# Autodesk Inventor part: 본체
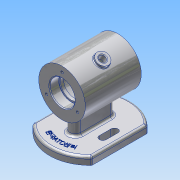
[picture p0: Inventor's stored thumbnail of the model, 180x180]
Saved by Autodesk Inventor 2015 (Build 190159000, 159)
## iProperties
Created: 2022-02
Part Number: 본체
Material: 알루미늄 6061
Document SubType Name: Modeling
Designer: 학생용
Density: 2.7 g/cm^3
Appearance: 알루미늄 - 평지
Mass: 495.267 g
Surface Area: 489.781 cm^2
Volume: 183.432 cm^3
Author: 학생용
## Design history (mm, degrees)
sketch "스케치1"
  geometry: L1 (0, 0)-(72, 0); L2 (72, 0)-(72, 30); L3 (72, 30)-(0, 30); L4 (0, 30)-(0, 0); L5 (0, 16)-(12, 16); L6 (12, 16)-(12, 14); L7 (12, 14)-(16, 14); L8 (16, 14)-(16, 25); L9 (16, 25)-(56, 25); L10 (56, 25)-(56, 14); L11 (56, 14)-(60, 14); L12 (60, 14)-(60, 16); L13 (60, 16)-(72, 16)
  constraints: 26 end point, 9 perpendicular, 6 point on line, 2 collinear, 2 horizontal
  dimensions: "d0" = 72 distance of L2.end L3.end; "d1" = 60 diameter of L3 L1; "d2" = 50 diameter of L9 L1; "d3" = 32 diameter of L13 L1; "d4" = 28 diameter of L11 L1; "d5" = 40 distance of L8.end L9.end; "d6" = 12 distance of L5.start L5.end
revolve "회전1" sketch "스케치1" stored, may be unused: angle "d7" = 90 deg
node "작업 평면2"
  node "작업 평면1"
sketch "스케치2"
  geometry: L1 (-0.504, -38)-(-71.496, -38); L2 (-0.504, 38)-(-71.496, 38); L3 (0, 30)-(0, -30) reference; L4 (-72, 30)-(-72, -30) reference; L5 (0, -30)-(-72, -30) reference; A1 r 52 centre (-36, 0) between (-0.504, -38) and (-0.504, 38); A2 r 52 centre (-36, 0) between (-71.496, 38) and (-71.496, -38); 4 further points
  constraints: 4 end point, 4 point on circle, 3 midpoint, 3 vertical alignment, 2 centre point, 2 horizontal, 1 coincident, 1 concentric, 1 horizontal alignment, 1 parallel
  dimensions: "d9" = 76 distance between parallel lines of L2 L1; "d10" = 52 radius of A1
extrude "돌출1" join sketch "스케치2" distance "d11" = 10; taper "d12" = 0 deg
sketch "스케치3"
  geometry: L1 (28.5, 28.5)-(43.5, 28.5); L2 (28.5, 19.5)-(43.5, 19.5); L3 (0.504, 38)-(71.496, 38) reference; A1 r 4.5 centre (28.5, 24) between (28.5, 28.5) and (28.5, 19.5); A2 r 4.5 centre (43.5, 24) between (43.5, 19.5) and (43.5, 28.5); 3 further points
  constraints: 4 end point, 4 point on circle, 3 vertical alignment, 2 centre point, 2 horizontal, 2 midpoint, 1 equal radius, 1 parallel, 1 tangent
  dimensions: "d13" = 15 distance of A2.centre A1.centre; "d14" = 9 distance between parallel lines of L2 L1; "d15" = 24 vertical distance of A1.centre point (0, 0)
extrude "돌출2" cut sketch "스케치3" distance "d16" = 10; taper "d17" = 0 deg
node "작업 평면3"
node "작업 평면4"
sketch "스케치4"
  geometry: L1 (28.5, 28.5)-(43.5, 28.5) reference; C1 r 42.5 at (36, 0); 2 further points
  constraints: 1 centre point, 1 horizontal alignment, 1 midpoint, 1 vertical alignment, 1 other
  dimensions: "d19" = 85 diameter of C1
feature "엠보싱1" sketch "스케치4" dims "d9" = 76, "d10" = 52, "d20" = 0.5, "d21" = 0
sketch "스케치5"
  geometry: L1 (17, 7)-(55, 7); L2 (17, -7)-(55, -7); L3 (0.504, 38)-(71.496, 38) reference; A1 r 7 centre (17, 0) between (17, 7) and (17, -7); A2 r 7 centre (55, 0) between (55, -7) and (55, 7); 3 further points
  constraints: 4 end point, 4 point on circle, 4 tangent, 2 centre point, 2 horizontal, 2 midpoint, 1 horizontal alignment, 1 vertical alignment
  dimensions: "d22" = 14 distance between parallel lines of L2 L1; "d23" = 38 distance of L2.start L2.end
extrude "돌출3" join sketch "스케치5" stored distance "d24" = 10; taper "d25" = 0 deg
node "작업 평면5"
sketch "스케치6"
  geometry: L1 (0, 0)-(0, 30); L2 (0, 0)-(16.5, 28.579); 1 further point
  constraints: 4 end point, 1 vertical, 1 vertical alignment, 1 other
  dimensions: "d26" = 30 deg angle of L2 L1; "d27" = 33 distance of L1.start L2.end
node "작업 평면6"
sketch "스케치7"
  geometry: C1 r 8 at (0, 0); C2 r 4 at (0, 0); 2 further points
  constraints: 2 centre point, 2 coincident
  dimensions: "d28" = 16 diameter of C1; "d29" = 8 diameter of C2
extrude "돌출4" join sketch "스케치7" stored distance "d30" = 10; taper "d31" = 0 deg
extrude "돌출5" cut sketch "스케치7" stored distance "d32" = 8; taper "d33" = 0 deg
sketch "스케치8" dims "d34" = 46
  geometry: 3 further points
  constraints: 2 vertical alignment, 1 coincident, 2 other
hole "구멍1" sketch "스케치8" at (0, 23) diameter "d35" = 3.242; stored, may be unused: countersink angle "d39" = 90 deg, drill point angle "d41" = 118 deg; dims "d36" = 8, "d37" = 4, "d38" = 2, "d40" = 10
chamfer "모따기1" distance "d45" = 1; stored, may be unused: second distance "d46" = 2, angle "d47" = 45 deg
fillet "모깎기1" dims "d48" = 0.3
fillet "모깎기2" dims "d49" = 3
fillet "모깎기3" dims "d50" = 1
fillet "모깎기4" dims "d51" = 3
fillet "모깎기5" dims "d52" = 3
fillet "모깎기6" dims "d53" = 3
fillet "모깎기7" dims "d54" = 3
fillet "모깎기8" dims "d55" = 1
node "솔리드1"
mirror "대칭1"
pattern_circular "원형 패턴1" dims angle "d43" = 360 deg
mirror "대칭2"
node "투영된 루프1"
other parameters: "d8" = -62
